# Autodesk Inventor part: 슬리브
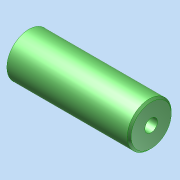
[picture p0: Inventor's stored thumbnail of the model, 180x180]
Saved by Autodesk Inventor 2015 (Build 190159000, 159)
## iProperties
Created: 2026-09
Part Number: 슬리브
Material: 일반
Document SubType Name: Modeling
Designer: SCD-A06
Density: 1 g/cm^3
Appearance: 기본값
Author: jhkim
Creation Date: 2026-08-27
Sending System: Autodesk Inventor 2027
Preprocessor: ST-DEVELOPER v20.1
Author: SCD-A06
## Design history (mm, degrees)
node "슬리브1"
node "솔리드1"
node "기준1"
